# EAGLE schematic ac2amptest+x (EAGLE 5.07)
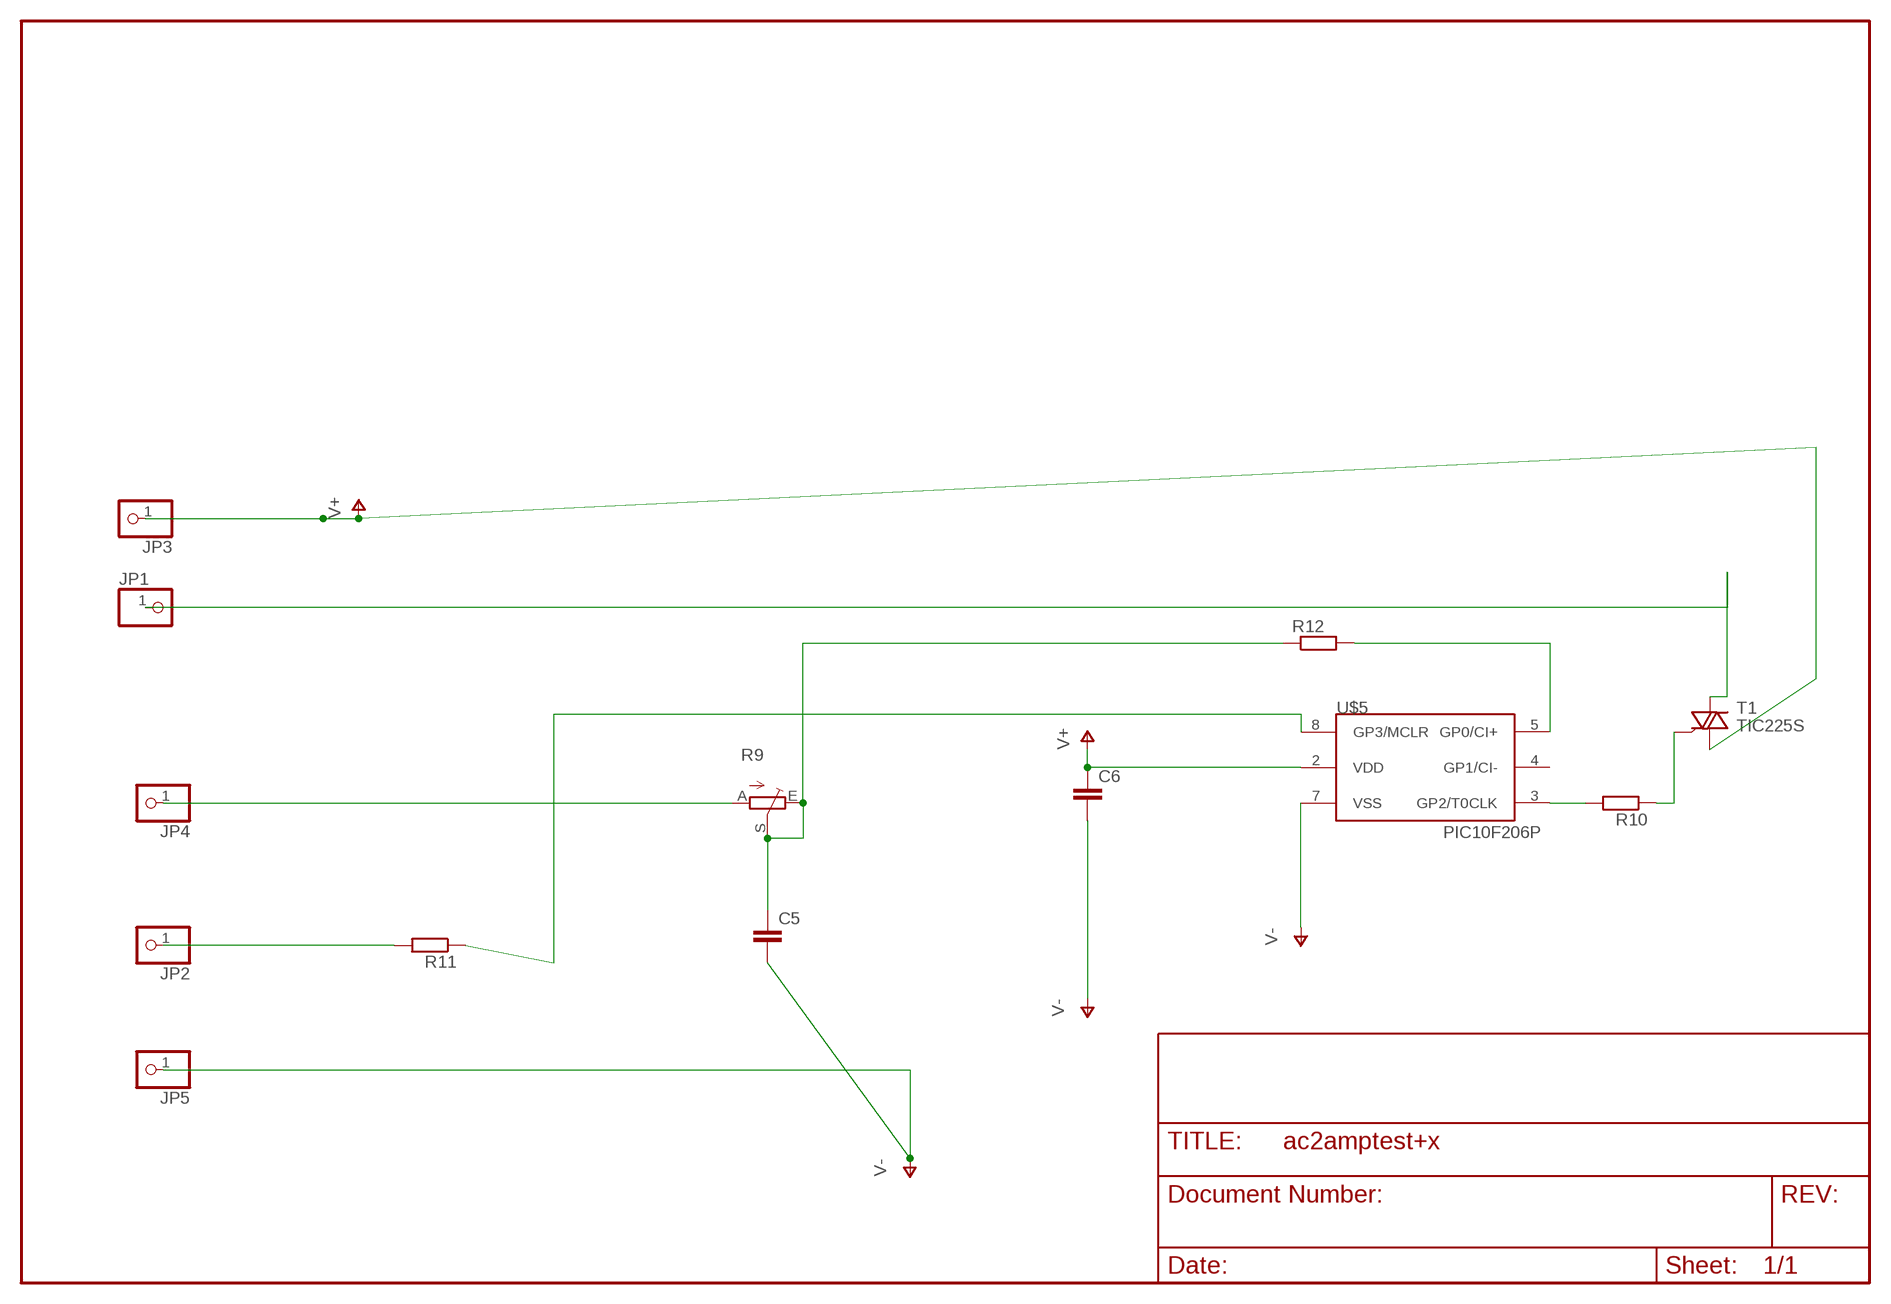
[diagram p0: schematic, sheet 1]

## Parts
C5  C-EU050-024X044  [C050-024X044]
C6  C-EU050-024X044  [C050-024X044]
JP1  PINHD-1X1  [1X01]
JP2  PINHD-1X1  [1X01]
JP3  PINHD-1X1  [1X01]
JP4  PINHD-1X1  [1X01]
JP5  PINHD-1X1  [1X01]
R9  TRIM_EU-LI15  [LI15]
R10  R-EU_0207/15  [0207/15]
R11  R-EU_0207/15  [0207/15]
R12  R-EU_0207/15  [0207/15]
T1  TIC225S  [TO220DS]
U$5  PIC10F206P  [DIL8]

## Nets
GATE: R10.1 T1.G
GP0: R12.2 U$5.5(GP0/CI+)
GP3: R11.1 U$5.8(GP3/MCLR)
N$1: JP4.1 R9.A
N$3: JP2.1 R11.2
N$9: C5.1 R9.E R9.S R12.1
N$11: JP1.1 T1.A2
N$20: R10.2 U$5.3(GP2/T0CLK)
V+: C6.1 JP3.1 T1.A1 U$5.2(VDD)
V-: C5.2 C6.2 JP5.1 U$5.7(VSS)
Unconnected: U$5.4(GP1/CI-)

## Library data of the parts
C5 C6 = rcl:C-EU: CAPACITOR, European symbol
JP1-JP5 = pinhead(2):PINHD-1X1: PIN HEADER
R9 = pot:TRIM_EU-: POTENTIOMETER
R10-R12 = rcl:R-EU_: RESISTOR, European symbol
T1 = triac:TIC225S: TRIAC
U$5 = microchip-3:PIC10F2*: uPC nW 0,25/0,5k Program Flash memory Comparator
